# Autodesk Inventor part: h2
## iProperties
Author: Administrator
Created: 2002-02
Part Number: h2
Document SubType Name: ﾓﾃﾞﾘﾝｸﾞ
Designer: Administrator
Control State: 0
Master: False
Checked Out: False
PropertySet Name: Design Tracking Control
Shininess: 64.0
Angle Display Precision: 2
Document Length Units: 11269
Document Angle Units: 11284
Document Time Units: 11279
Document Mass Units: 11290
Document Length Units Precision: 2
Document Angle Units Precision: 1
Compacted: True
PropertySet Name: _Private Model Information
Density: 0.0
Volumn: 0.0
Area: 0.0
PropertySet Name: Model Information
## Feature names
1. 押し出し1 [Extrusion]
